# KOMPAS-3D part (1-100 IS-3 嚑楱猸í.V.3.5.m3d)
File: created 28.02.2017 20:54:14, last saved 28.02.2017 21:05:26.
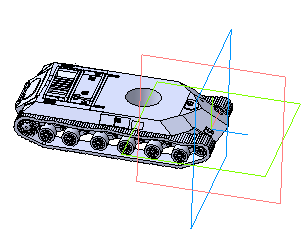
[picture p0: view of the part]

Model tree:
1. Операция без истории:1
2. Операция без истории:2
3. Операция без истории:3
4. Операция без истории:4
5. Операция без истории:5
6. Операция без истории:6
7. Операция выдавливания:1
     Расстояние 1 = 0.1
8. Вырезать элемент выдавливания:1
     Расстояние 1 = 0.1
9. Вырезать элемент выдавливания:2
     Расстояние 1 = 0.1
10. Вырезать элемент выдавливания:3
     Расстояние 1 = 0.1
11. Операция выдавливания:2
     Расстояние 1 = 0.1
12. Операция выдавливания:3
     Расстояние 1 = 0.1
13. Операция выдавливания:4
     Расстояние 1 = 0.1
14. Вырезать элемент выдавливания:4
     Расстояние 1 = 0.1
15. Вырезать элемент выдавливания:5
     Расстояние 1 = 0.1
16. Вырезать элемент выдавливания:6
     Расстояние 1 = 0.1
17. Вырезать элемент выдавливания:7
     Расстояние 1 = 0.1
18. Вырезать элемент выдавливания:8
     Расстояние 1 = 0.1
19. Вырезать элемент выдавливания:9
     Расстояние 1 = 0.1
20. Вырезать элемент выдавливания:10
     Расстояние 1 = 0.1
21. Вырезать элемент выдавливания:11
     Расстояние 1 = 0.1
22. Вырезать элемент выдавливания:12
     Расстояние 1 = 0.1
23. Вырезать элемент выдавливания:13
     Расстояние 1 = 0.1
24. Вырезать элемент выдавливания:14
     Расстояние 1 = 0.1
25. Вырезать элемент выдавливания:15
     Расстояние 1 = 0.1
26. Вырезать элемент выдавливания:16
     Расстояние 1 = 0.1
27. Вырезать элемент выдавливания:17
     Расстояние 1 = 0.1
28. Вырезать элемент выдавливания:18
     Расстояние 1 = 0.1
29. Вырезать элемент выдавливания:19
     Расстояние 1 = 0.1
30. Вырезать элемент выдавливания:20
     Расстояние 1 = 0.1
31. Вырезать элемент выдавливания:21
     Расстояние 1 = 0.1
32. Вырезать элемент выдавливания:22
     Расстояние 1 = 0.1
33. Вырезать элемент выдавливания:23
     Расстояние 1 = 0.1
34. Вырезать элемент выдавливания:24
     Расстояние 1 = 0.1
35. Вырезать элемент выдавливания:25
     Расстояние 1 = 0.1
36. Вырезать элемент выдавливания:26
     Расстояние 1 = 0.1
37. Вырезать элемент выдавливания:27
     Расстояние 1 = 0.1
38. Вырезать элемент выдавливания:28
     Расстояние 1 = 0.1
39. Вырезать элемент выдавливания:29
     Расстояние 1 = 0.1
40. Вырезать элемент выдавливания:30
     Расстояние 1 = 0.1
